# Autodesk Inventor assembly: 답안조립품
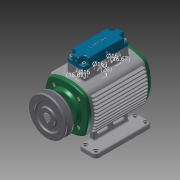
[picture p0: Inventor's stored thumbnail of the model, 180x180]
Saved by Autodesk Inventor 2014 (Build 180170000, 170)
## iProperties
Created: 2015-11
Part Number: 답안조립품
Document SubType Name: Assembly
Designer: SEC
Author: SEC
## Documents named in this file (18)
- C:\Users\SEC\Desktop\351109V1021\답안조립품.iam
- C:\Users\SEC\Desktop\351109V1021\본체.ipt
- C:\Users\SEC\Desktop\351109V1021\뒷커버.ipt
- C:\Users\SEC\Desktop\351109V1021\볼트 M4 x 12.ipt
- C:\Users\SEC\Desktop\351109V1021\베어링 6203.ipt
- C:\Users\SEC\Desktop\351109V1021\앞커버.ipt
- C:\Users\SEC\Desktop\351109V1021\오일실 17 30 8.ipt
- C:\Users\SEC\Desktop\351109V1021\축.ipt
- C:\Users\SEC\Desktop\351109V1021\키 - 5 x 5 x 18.ipt
- C:\Users\SEC\Desktop\351109V1021\V-벨트풀리.ipt
- C:\Users\SEC\Desktop\351109V1021\멈춤나사 M4x5.ipt
- C:\Users\SEC\Desktop\351109V1021\부시.ipt
- C:\Users\SEC\Desktop\351109V1021\헤더커버.ipt
- C:\Users\SEC\Desktop\351109V1021\볼트 M4 x 16.ipt
- C:\Users\SEC\Desktop\351109V1021\슬라이드.ipt
- C:\Users\SEC\Desktop\351109V1021\15.스프링.ipt
- C:\Users\SEC\Desktop\351109V1021\16.스프링.ipt
- C:\Users\SEC\Desktop\351109V1021\17.스프링.ipt
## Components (7 placed, 6 different names)
1. 7-베어링 6203:1
2. 7-베어링 6203:2
3. V-벨트풀리:1 — 각도:4
4. 헤더커버:1
5. 15.스프링:1
6. 16.스프링:1
7. 17.스프링:1
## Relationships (1: Angle 1)
- 각도:4 [Angle]: V-벨트풀리:1
